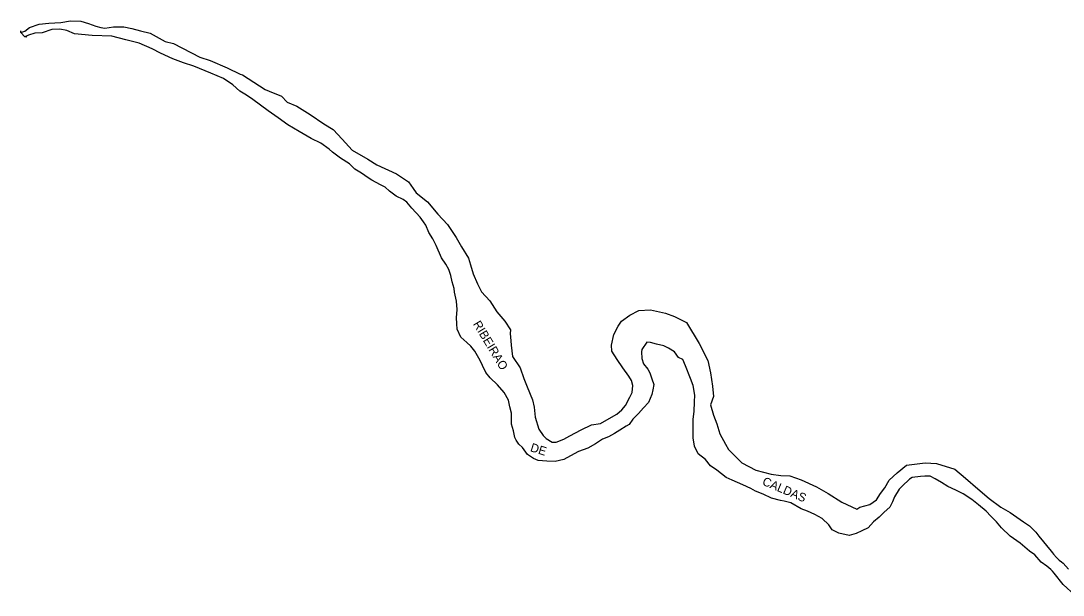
# Model space of a CAD drawing. Extents: x 325899 to 364828, y 7568995 to 7592502.
# Drawn here: x 338797.2 to 339281.4, y 7587552.1 to 7587818.8 of the extents above; entities that cross this region are included whole.
import ezdxf

# ---------------------------------------------------------------- set-up
doc = ezdxf.new("R2010")
doc.units = 0
for name, color, linetype in [('EDIFEXISTENT', 7, 'Continuous'), ('EDIFIDENTIF', 7, 'Continuous'), ('EDIFOBRAEXIS', 7, 'Continuous')]:
    doc.layers.add(name, color=color, linetype=linetype)

msp = doc.modelspace()

# ---------------------------------------------------------------- linework, layer by layer
at = {"layer": 'EDIFEXISTENT'}
for p, q in [((338797.18, 7587813.42), (338797.18, 7587814.15)), ((338799.07, 7587811.42), (338797.18, 7587813.42)), ((338799.91, 7587811.28), (338799.07, 7587811.42))]:
    msp.add_line(p, q, dxfattribs=at)
at = {"layer": 'EDIFOBRAEXIS'}
for points in [[(338797.18, 7587813.42), (338798.98, 7587814.06), (338801.23, 7587815.7), (338805.65, 7587817.32), (338810.19, 7587817.73), (338815.82, 7587818.05), (338820.23, 7587818.81), (338825.1, 7587818.71), (338828.63, 7587817.65), (338832.01, 7587816.35), (338834.33, 7587815.7), (338836.23, 7587815.44), (338840.21, 7587816.04), (338845.05, 7587816), (338848.76, 7587815.26), (338852.72, 7587814.14), (338857.19, 7587813.03), (338864.22, 7587809.19), (338868.03, 7587808.3), (338880.27, 7587802.01), (338885.2, 7587800.34), (338893.06, 7587796.92), (338899.04, 7587794.04), (338900.16, 7587793.72), (338910.62, 7587786.91), (338912.53, 7587786.13), (338918.2, 7587783.81), (338920.83, 7587781.09), (338925.36, 7587779.14), (338931.57, 7587775.39), (338937.99, 7587771.02), (338942.26, 7587768.41), (338946.4, 7587763.9), (338951.1, 7587758.73), (338958.3, 7587754.59), (338962.48, 7587751.87), (338971.69, 7587747.72), (338977.27, 7587744.02), (338979.39, 7587740.92), (338980.8, 7587738.95), (338986.02, 7587734.75), (338990.95, 7587729.07), (338995.45, 7587724.25), (338999.47, 7587718.16), (339001.85, 7587713.79), (339005.08, 7587708.64), (339006.12, 7587705.5), (339007.23, 7587701.27), (339009.27, 7587696.69), (339011.24, 7587692.98), (339015.1, 7587688.81), (339018.33, 7587683.71), (339021.98, 7587679.27), (339024.62, 7587675.25), (339024.55, 7587673.65), (339024.85, 7587670.21), (339024.92, 7587668.18), (339025.61, 7587662.93), (339029.12, 7587657.7), (339030.87, 7587652.79), (339032.39, 7587648.85), (339034.84, 7587642.83), (339035.62, 7587639.41), (339036.08, 7587634.72), (339037.79, 7587629.22), (339039.84, 7587626.29), (339041.29, 7587624.93), (339043.94, 7587623.22), (339045.84, 7587623.14), (339049.44, 7587624.58), (339052.24, 7587626.12), (339057.5, 7587628.86), (339062.23, 7587631.18), (339066.51, 7587631.84), (339070.45, 7587634.14), (339074.02, 7587636.09), (339076.41, 7587638.16), (339078.08, 7587640.2), (339080.13, 7587644.1), (339081.13, 7587646.28), (339081.52, 7587649.48), (339080.82, 7587651.84), (339079.59, 7587653.86), (339076.9, 7587657.75), (339074.19, 7587661.61), (339071.65, 7587665.48), (339071.51, 7587668.19), (339072.62, 7587673.12), (339074.65, 7587676.96), (339076.16, 7587679.4), (339080.1, 7587682.14), (339084.32, 7587684.27), (339089.67, 7587684.61), (339096.65, 7587683.03), (339100.82, 7587681.54), (339106.4, 7587678.68), (339112.24, 7587668.92), (339116.27, 7587661.06), (339117.57, 7587655.41), (339118.45, 7587649.23), (339118.91, 7587644.31), (339117.59, 7587640.42), (339118.89, 7587635.76), (339120.46, 7587631.61), (339121.94, 7587627.08), (339124.55, 7587622.18), (339125.94, 7587619.68), (339132.19, 7587613.55), (339138.7, 7587610.19), (339145.72, 7587608.26), (339150.26, 7587607.65), (339154.47, 7587607.53), (339159.71, 7587605.66), (339166.83, 7587602.48), (339172.3, 7587599.32), (339178.64, 7587595.27), (339185.61, 7587592.1), (339186.9, 7587593.02), (339191.64, 7587594.16), (339194.62, 7587596.34), (339196.48, 7587599.27), (339198.56, 7587601.89), (339200.52, 7587605.48), (339204.3, 7587608.9), (339208.54, 7587612.4), (339217.26, 7587613.57), (339222.49, 7587613.23), (339231.08, 7587610.54), (339236.08, 7587606.49), (339241.71, 7587601.53), (339247.02, 7587596.99), (339252.44, 7587592.99), (339256.85, 7587590.56), (339262.94, 7587586.11), (339265.76, 7587584.33), (339268.67, 7587581.35), (339270.03, 7587579.58), (339275.75, 7587572.57), (339276.4, 7587571.78), (339276.87, 7587571.1), (339278.24, 7587569.62), (339279.57, 7587568.39), (339280.62, 7587567.6), (339281.39, 7587566.92)], [(339281.39, 7587557.13), (339277.19, 7587562.28), (339276.47, 7587563.2), (339275.68, 7587564.1), (339273.79, 7587565.58), (339271.24, 7587567.47), (339268.31, 7587570.85), (339265.76, 7587572.56), (339261.42, 7587576.21), (339256.84, 7587579.48), (339252.81, 7587583.31), (339250.35, 7587586.16), (339247.76, 7587588.86), (339245.63, 7587591.1), (339242.11, 7587594.1), (339238.93, 7587596.51), (339234.95, 7587599.1), (339231.47, 7587600.9), (339227.78, 7587602.58), (339224.9, 7587604.44), (339222, 7587606.12), (339219.66, 7587607.3), (339217.15, 7587607.36), (339215.09, 7587607.19), (339211.32, 7587606.69), (339209.98, 7587605.92), (339206.57, 7587602.7), (339205.14, 7587601.4), (339203.11, 7587597.71), (339202.11, 7587595.4), (339200.9, 7587592.93), (339198.2, 7587590.58), (339195.96, 7587588.36), (339193.26, 7587586.18), (339190.77, 7587583.45), (339187.88, 7587581.97), (339185.3, 7587580.76), (339181.94, 7587579.82), (339177.14, 7587580.83), (339174.01, 7587582.51), (339172.5, 7587584.84), (339169.46, 7587587.63), (339166.05, 7587589.49), (339162.69, 7587591.09), (339159.67, 7587592.24), (339154.88, 7587595.03), (339151.76, 7587595.72), (339150.05, 7587596.09), (339145.89, 7587597.13), (339141.97, 7587598.93), (339138.46, 7587600.4), (339136.27, 7587601.71), (339132.61, 7587603.28), (339127.65, 7587605.56), (339124.8, 7587606.68), (339120.54, 7587610.08), (339117.54, 7587612.09), (339115.29, 7587615.04), (339111.87, 7587617.81), (339110.13, 7587621.28), (339109.54, 7587625.1), (339109.45, 7587628.3), (339109.51, 7587630.79), (339109.57, 7587633.88), (339109.98, 7587637.43), (339110.2, 7587641.85), (339110.21, 7587644.99), (339109.47, 7587649.45), (339108.33, 7587652.77), (339106.01, 7587658.54), (339104.65, 7587661.55), (339102.72, 7587662.47), (339100.77, 7587665.05), (339098.02, 7587666.83), (339095.89, 7587667.83), (339092.41, 7587668.6), (339089.69, 7587669.44), (339088.01, 7587669.61), (339085.6, 7587666.17), (339085.48, 7587665.08), (339085.65, 7587662.01), (339086.43, 7587659.46), (339088.47, 7587656.98), (339089.4, 7587655.29), (339090.33, 7587652.56), (339091.2, 7587649.92), (339090.84, 7587647.46), (339090.27, 7587645.3), (339088.82, 7587641.54), (339086.38, 7587639.16), (339084.11, 7587636.49), (339081.44, 7587633.78), (339079.73, 7587631.41), (339078.36, 7587630.52), (339075.46, 7587628.67), (339073.01, 7587627.16), (339070.15, 7587625.67), (339067.37, 7587624.49), (339064.21, 7587622.39), (339060.62, 7587620.41), (339056.24, 7587618.79), (339052.58, 7587616.76), (339049.37, 7587615.09), (339045.37, 7587614.2), (339041.56, 7587614.28), (339037.47, 7587614.71), (339035.39, 7587615.51), (339032.49, 7587617.4), (339030.21, 7587620.73), (339028.52, 7587622.16), (339027.32, 7587624.06), (339026.63, 7587625.3), (339026.05, 7587628.39), (339025.19, 7587631.45), (339025.11, 7587632.67), (339025.19, 7587636.68), (339024.33, 7587639.64), (339023.76, 7587642.71), (339021.76, 7587646.19), (339018.64, 7587649.78), (339015.27, 7587653.03), (339013.2, 7587655.52), (339011.58, 7587658.71), (339010.55, 7587661.01), (339008.02, 7587665.41), (339006.2, 7587667.81), (339004.34, 7587669.39), (339001.53, 7587671.94), (338999.94, 7587675.56), (338999.72, 7587678.07), (338999.6, 7587681.01), (338999.66, 7587682.73), (338999.91, 7587684.76), (338999.6, 7587688.69), (338998.66, 7587692.82), (338998.42, 7587694.52), (338997.54, 7587697.61), (338996.99, 7587700.57), (338995.99, 7587703.31), (338994.57, 7587705.86), (338992.6, 7587708.81), (338990.11, 7587714.48), (338988.54, 7587717.64), (338986.77, 7587720.55), (338985.28, 7587723.86), (338984.31, 7587725.5), (338982.67, 7587727.72), (338978.86, 7587731.86), (338976.44, 7587734.63), (338974.83, 7587735.87), (338971.55, 7587737.39), (338968.39, 7587739.73), (338966.5, 7587741.52), (338964.24, 7587742.68), (338960.17, 7587744.88), (338958.49, 7587745.94), (338955.4, 7587748.02), (338952.3, 7587750.01), (338949.85, 7587752.45), (338945.62, 7587755.06), (338941.93, 7587757.76), (338940.37, 7587759.24), (338936.55, 7587762.06), (338932.02, 7587764.21), (338926.52, 7587767.35), (338921.2, 7587770.49), (338916.79, 7587773.78), (338912, 7587776.97), (338904.97, 7587782.26), (338901.96, 7587784.27), (338898.96, 7587786.15), (338895.72, 7587789.15), (338891.31, 7587792.06), (338885.41, 7587794.49), (338877.56, 7587797.81), (338872.8, 7587799.28), (338867.77, 7587801.25), (338862.07, 7587803.83), (338858.23, 7587805.78), (338852.13, 7587808.41), (338845.88, 7587810.04), (338839.52, 7587811.75), (338830.29, 7587812), (338822.07, 7587812.71), (338818.51, 7587814.39), (338815.33, 7587815), (338811.55, 7587814.83), (338807.12, 7587813.28), (338803.6, 7587813.03), (338800.79, 7587812.2), (338799.07, 7587811.42)], [(339281.39, 7587566.92), (339283.8, 7587564.24)], [(339281.39, 7587557.13), (339286.86, 7587552.11)]]:
    msp.add_lwpolyline(points, dxfattribs=at)

# ---------------------------------------------------------------- texts
at = {"layer": 'EDIFIDENTIF'}
for s, rotation, p in [('RIBEIRAO', 301.0913, (339007.09, 7587678.07)), ('DE', 342.649, (339033.54, 7587619.02)), ('CALDAS', 337.0192, (339141.29, 7587603.5))]:
    msp.add_text(s, height=4, rotation=rotation, dxfattribs=at).set_placement(p)

doc.saveas('drawing.dxf')
